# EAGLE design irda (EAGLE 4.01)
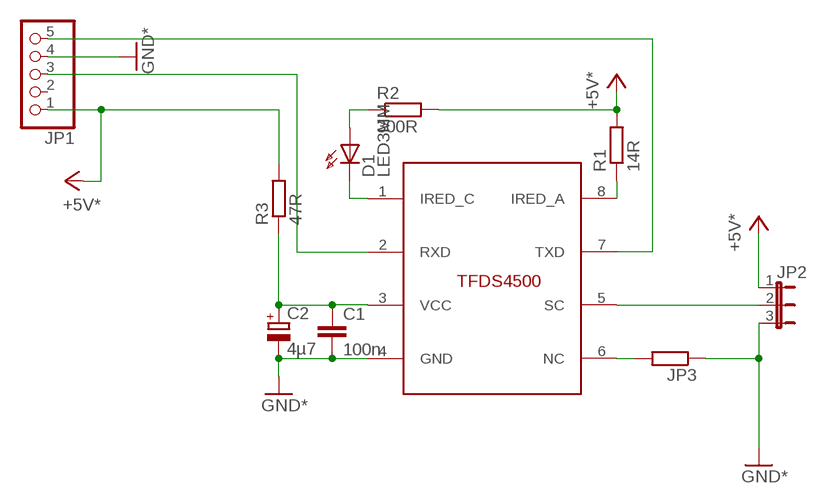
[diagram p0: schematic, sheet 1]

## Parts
C1  100n  C-EUC1206  [C1206]
C2  4µ7  CPOL-EUCT7343  [CT7343]
D1  LED3MM  [LED3MM]
JP1  PINHD-1X5  [1X05]
JP2  JP2E  [JP2]
JP3  R-EU_R0805  [R0805]
R1  14R  R-EU_R1206  [R1206]
R2  300R  R-EU_R1206  [R1206]
R3  47R  R-EU_R1206  [R1206]
TFDS4500  TFDS4500TFDS4500  [TFDS4500]

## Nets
+5V: JP1.1 JP2.1 R1.2 R2.2 R3.2 ; supply symbol labelled +5V*
GND: C1.1 C2.- JP1.4 JP2.3 JP3.1 TFDS4500.4(GND) ; supply symbol labelled GND*
N$1: R1.1 TFDS4500.8(IRED_A)
N$2: D1.K(C) TFDS4500.1(IRED_C)
N$3: JP3.2 TFDS4500.6(NC)
N$4: D1.A R2.1
RXD: JP1.3 TFDS4500.2(RXD)
SENSE_CTRL: JP2.2 TFDS4500.5(SC)
TXD: JP1.5 TFDS4500.7(TXD)
VCC_FILTERED: C1.2 C2.+ R3.1 TFDS4500.3(VCC)
Unconnected: JP1.2

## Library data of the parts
C1 = rcl:C-EU: CAPACITOR, European symbol
C2 = rcl:CPOL-EU: POLARIZED CAPACITOR, European symbol
D1 = led:LED3MM: LED
JP1 = pinhead:PINHD-1X5: PIN HEADER
JP2 = jumper:JP2E: JUMPER
JP3 R1-R3 = rcl:R-EU_: RESISTOR, European symbol
TFDS4500 = irda:TFDS4500: Vishay Telefunken TFDS4500 IrDA Transceiver. Side view type.

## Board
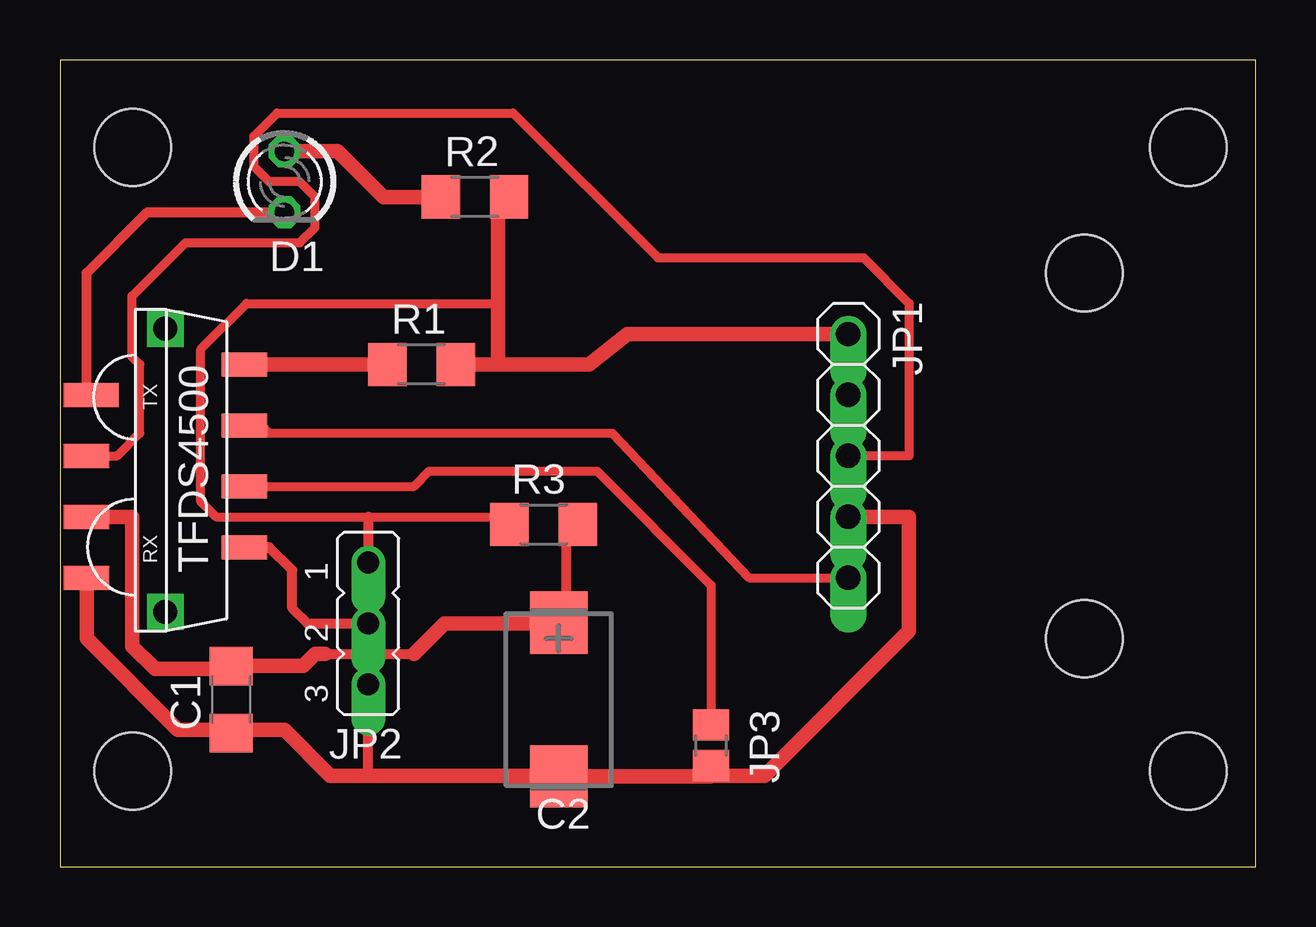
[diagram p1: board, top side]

Size 49.84 x 33.64 mm. Coordinates in mm from the lower left corner, seen from the top.
Outline: 0,0 49.84,0 49.84,33.64 0,33.64 0,0
Copper layers used: Top
Holes 3.2 mm at 3.04,30 3.04,4 47.04,4 47.04,30 42.7,24.76 42.7,9.52

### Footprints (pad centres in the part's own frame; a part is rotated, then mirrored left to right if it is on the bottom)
C1206 = smd 1.6 x 1.8: 1 -1.4,0; 2 1.4,0
CT7343 = smd 2.6 x 2.4: + -3.2,0; - 3.2,0
LED3MM = drill 0.813 octagon: A -1.27,0; K 1.27,0
1X05 = drill 1.016 offset: 1 -5.08,0; 2 -2.54,0; 3 0,0; 4 2.54,0; 5 5.08,0
JP2 = drill 0.914 offset: 1 -2.54,0; 2 0,0; 3 2.54,0
R0805 = smd 1.3 x 1.5: 1 -0.85,0; 2 0.85,0
R1206 = smd 1.6 x 1.803: 1 -1.422,0; 2 1.422,0
TFDS4500 = smd 1 x 2.3: 1 -2.54,-2.34 | smd 1 x 1.9: 2 0,-2.54; 3 2.54,-2.54; 4 5.08,-2.54; 5 3.81,4.04; 6 1.27,4.04; 7 -1.27,4.04; 8 -3.81,4.04 | drill 1 square: GND_1 -5.3,0.75; GND_2 6.5,0.75

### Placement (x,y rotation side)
C1  7.14,6.98 90 top
C2  20.79,6.98 270 top
D1  9.36,28.57 270 top
JP1  32.86,17.14 270 top
JP2  12.85,10.15 270 top
JP3  27.14,5.08 90 top
R1  15.07,20.95 0 top
R2  17.3,27.93 0 top
R3  20.15,14.28 180 top
TFDS4500  3.65,17.14 270 top

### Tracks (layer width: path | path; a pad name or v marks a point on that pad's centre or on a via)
+5V
  Top 0.381: 18.25,23.49 7.77,23.49 5.87,21.59 5.87,15.23 6.5,14.6 12.85,14.6 19.2,14.6 R3.2
  Top 0.406: 12.85,14.6 JP2.1
  Top 0.61: 18.25,20.95 18.25,23.49 18.25,27.3 R2.2 | 18.25,20.95 R1.2 | 18.25,20.95 22.06,20.95 23.65,22.22 JP1.1
GND
  Top 0.406: 20.79,3.81 C2.- | 27.14,4.44 JP3.1 27.14,3.81 27.14,3.78 | 12.85,3.81 JP2.3
  Top 0.61: TFDS4500.4 1.1,9.52 4.92,5.71 7.14,5.71 C1.1 7.24,5.71 9.36,5.71 11.26,3.81 12.85,3.81 20.79,3.81 | C2.- 27.14,3.78 | JP1.4 35.4,14.6 35.4,9.84 29.36,3.81 27.14,3.81
N$1
  Top 0.381: 8.41,20.95 8.72,20.95
  Top 0.61: TFDS4500.8 8.41,20.95 | 8.72,20.95 R1.1
N$2
  Top 0.406: D1.K 3.65,27.3 1.1,24.76 1.1,19.68 TFDS4500.1
N$3
  Top 0.381: JP3.2 27.14,5.71 27.14,11.74 22.38,16.5 15.39,16.5 14.76,15.87 TFDS4500.6
N$4
  Top 0.61: D1.A 11.58,29.84 13.49,27.93 R2.1
RXD
  Top 0.381: TFDS4500.2 2.38,17.14 3.33,18.09 3.33,20.95 3.01,21.27 3.01,23.81 5.23,26.03 9.99,26.03 10.63,26.66 10.63,27.93 9.99,28.57 8.72,28.57 8.09,29.2 8.09,30.47 9.04,31.43 18.88,31.43 24.92,25.39 33.49,25.39 35.4,23.49 35.4,17.14 JP1.3
SENSE_CTRL
  Top 0.406: TFDS4500.5 8.72,13.33 9.68,12.38 9.68,10.79 10.31,10.15 JP2.2
TXD
  Top 0.381: TFDS4500.7 8.41,18.41 8.72,18.09 23.01,18.09 28.73,12.06 JP1.5
VCC_FILTERED
  Top 0.406: C2.+ 20.79,10.15 21.11,10.47 21.11,13.96 R3.1 | 11.05,8.88 14.76,8.88
  Top 0.61: 11.05,8.88 10.63,8.88 10.12,8.38 C1.2 6.82,8.25 3.96,8.25 3.01,9.2 3.01,14.6 TFDS4500.3 | 14.76,8.88 16.03,10.15 20.79,10.15

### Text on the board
Document: tscherwitschke | Ctl | (c) 2001 | + | R | - | Hi | T | Lo | 4500 open | 6500 close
